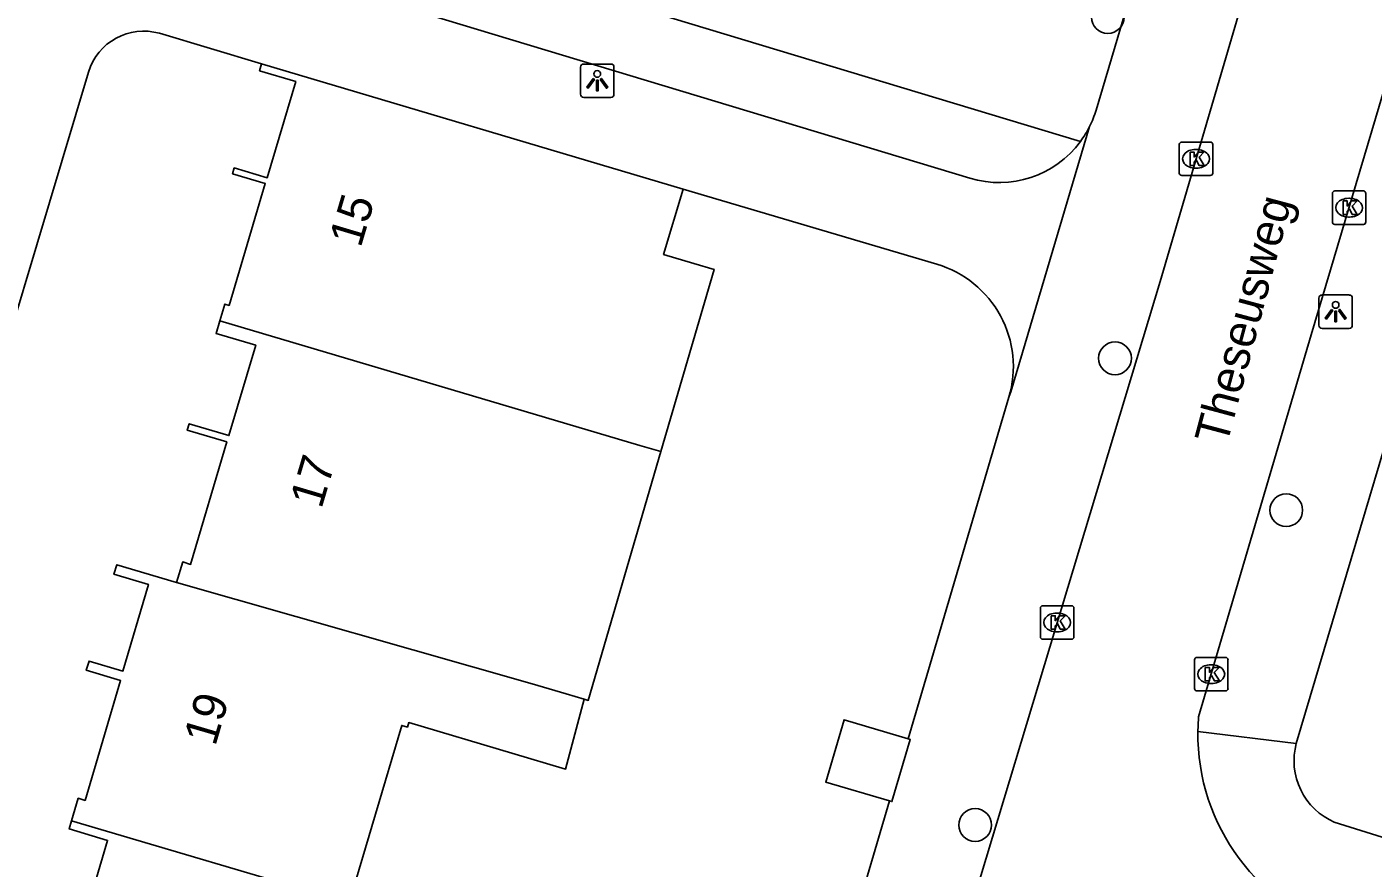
# Model space of a CAD drawing. Extents: x 162186 to 163152, y 385513 to 386513.
# Drawn here: x 162692.04 to 162732.25, y 386082.74 to 386107.85 of the extents above; entities that cross this region are included whole.
import ezdxf

# ---------------------------------------------------------------- set-up
doc = ezdxf.new("R2010")
doc.units = 0
for name, color, linetype in [('IMGEO_Boom', 7, 'Continuous'), ('IMGEO_Groenvoorziening', 7, 'Continuous'), ('IMGEO_Kolk', 7, 'Continuous'), ('IMGEO_Lichtpunt', 7, 'Continuous'), ('IMGEO_Openbare_ruimte_label', 7, 'Continuous'), ('IMGEO_Pand', 7, 'Continuous'), ('IMGEO_Pand_nummerreeks', 7, 'Continuous'), ('IMGEO_Rijbaan_lokaal_open', 7, 'Continuous'), ('IMGEO_Voetpad_open', 7, 'Continuous')]:
    doc.layers.add(name, color=color, linetype=linetype)

msp = doc.modelspace()

# ---------------------------------------------------------------- linework, layer by layer
at = {"layer": 'IMGEO_Boom'}
for centre in [(162724.33, 386108.149), (162724.546, 386097.96), (162729.661, 386093.425), (162720.367, 386084.025)]:
    msp.add_circle(centre, 0.489, dxfattribs=at)
at = {"layer": 'IMGEO_Groenvoorziening'}
msp.add_lwpolyline([(162701.905, 386126.5), (162697.912, 386113.179), (162697.874, 386112.633), (162698.083, 386112.243), (162698.513, 386111.989), (162723.511, 386104.431)], dxfattribs=at)
at = {"layer": 'IMGEO_Kolk'}
for p, q in [((162726.465, 386103.491), (162726.465, 386104.343)), ((162726.54, 386104.417), (162727.392, 386104.417)), ((162726.953, 386104.197), (162726.978, 386104.197)), ((162727.466, 386104.343), (162727.466, 386103.491)), ((162727.392, 386103.417), (162726.54, 386103.417)), ((162726.976, 386103.637), (162726.951, 386103.637)), ((162731.113, 386102.957), (162731.965, 386102.957)), ((162731.038, 386102.031), (162731.038, 386102.883)), ((162731.526, 386102.737), (162731.551, 386102.737)), ((162732.039, 386102.883), (162732.039, 386102.031)), ((162731.549, 386102.177), (162731.524, 386102.177)), ((162731.965, 386101.957), (162731.113, 386101.957)), ((162722.316, 386089.647), (162722.316, 386090.499)), ((162722.391, 386090.573), (162723.243, 386090.573)), ((162723.317, 386090.499), (162723.317, 386089.647)), ((162722.804, 386090.353), (162722.829, 386090.353)), ((162722.827, 386089.793), (162722.802, 386089.793)), ((162723.243, 386089.573), (162722.391, 386089.573)), ((162726.92, 386088.104), (162726.92, 386088.956)), ((162726.995, 386089.03), (162727.847, 386089.03)), ((162727.921, 386088.956), (162727.921, 386088.104)), ((162727.408, 386088.81), (162727.433, 386088.81)), ((162727.431, 386088.25), (162727.406, 386088.25)), ((162727.847, 386088.03), (162726.995, 386088.03))]:
    msp.add_line(p, q, dxfattribs=at)
for points in [[(162726.465, 386103.491), (162726.465, 386104.343)], [(162726.54, 386104.417), (162727.392, 386104.417)], [(162727.466, 386104.343), (162727.466, 386103.491)], [(162726.786, 386104.117), (162726.909, 386104.117), (162726.909, 386103.966), (162727.039, 386104.117), (162727.203, 386104.117), (162727.057, 386103.966), (162727.21, 386103.717), (162727.058, 386103.717), (162726.973, 386103.881), (162726.909, 386103.814), (162726.909, 386103.717), (162726.786, 386103.717), (162726.786, 386104.117)], [(162727.392, 386103.417), (162726.54, 386103.417)], [(162731.113, 386102.957), (162731.965, 386102.957)], [(162731.038, 386102.031), (162731.038, 386102.883)], [(162731.359, 386102.657), (162731.482, 386102.657), (162731.482, 386102.506), (162731.612, 386102.657), (162731.776, 386102.657), (162731.63, 386102.506), (162731.783, 386102.257), (162731.631, 386102.257), (162731.546, 386102.421), (162731.482, 386102.354), (162731.482, 386102.257), (162731.359, 386102.257), (162731.359, 386102.657)], [(162732.039, 386102.883), (162732.039, 386102.031)], [(162731.965, 386101.957), (162731.113, 386101.957)], [(162722.316, 386089.647), (162722.316, 386090.499)], [(162722.391, 386090.573), (162723.243, 386090.573)], [(162723.317, 386090.499), (162723.317, 386089.647)], [(162722.637, 386090.273), (162722.76, 386090.273), (162722.76, 386090.122), (162722.89, 386090.273), (162723.054, 386090.273), (162722.908, 386090.122), (162723.061, 386089.873), (162722.909, 386089.873), (162722.824, 386090.037), (162722.76, 386089.97), (162722.76, 386089.873), (162722.637, 386089.873), (162722.637, 386090.273)], [(162723.243, 386089.573), (162722.391, 386089.573)], [(162726.92, 386088.104), (162726.92, 386088.956)], [(162726.995, 386089.03), (162727.847, 386089.03)], [(162727.921, 386088.956), (162727.921, 386088.104)], [(162727.241, 386088.73), (162727.364, 386088.73), (162727.364, 386088.579), (162727.494, 386088.73), (162727.658, 386088.73), (162727.512, 386088.579), (162727.665, 386088.33), (162727.513, 386088.33), (162727.428, 386088.494), (162727.364, 386088.427), (162727.364, 386088.33), (162727.241, 386088.33), (162727.241, 386088.73)], [(162727.847, 386088.03), (162726.995, 386088.03)]]:
    msp.add_lwpolyline(points, dxfattribs=at)
for centre, start, end in [((162726.542, 386104.341), 91.552, 178.448), ((162726.542, 386104.341), 91.552, 178.448), ((162727.39, 386104.341), 1.552, 88.448), ((162727.39, 386104.341), 1.552, 88.448), ((162726.542, 386103.493), 181.552, 268.448), ((162726.542, 386103.493), 181.552, 268.448), ((162727.39, 386103.493), 271.552, 358.448), ((162727.39, 386103.493), 271.552, 358.448), ((162731.115, 386102.881), 91.552, 178.448), ((162731.115, 386102.881), 91.552, 178.448), ((162731.963, 386102.881), 1.552, 88.448), ((162731.963, 386102.881), 1.552, 88.448), ((162731.115, 386102.033), 181.552, 268.448), ((162731.115, 386102.033), 181.552, 268.448), ((162731.963, 386102.033), 271.552, 358.448), ((162731.963, 386102.033), 271.552, 358.448), ((162722.393, 386090.497), 91.552, 178.448), ((162722.393, 386090.497), 91.552, 178.448), ((162723.241, 386090.497), 1.552, 88.448), ((162723.241, 386090.497), 1.552, 88.448), ((162722.393, 386089.649), 181.552, 268.448), ((162722.393, 386089.649), 181.552, 268.448), ((162723.241, 386089.649), 271.552, 358.448), ((162723.241, 386089.649), 271.552, 358.448), ((162726.997, 386088.954), 91.552, 178.448), ((162726.997, 386088.954), 91.552, 178.448), ((162727.845, 386088.954), 1.552, 88.448), ((162727.845, 386088.954), 1.552, 88.448), ((162726.997, 386088.106), 181.552, 268.448), ((162726.997, 386088.106), 181.552, 268.448), ((162727.845, 386088.106), 271.552, 358.448), ((162727.845, 386088.106), 271.552, 358.448)]:
    msp.add_arc(centre, 0.0765, start, end, dxfattribs=at)
for centre, major_axis, ratio, start_param, end_param in [((162726.952, 386103.917), (-0.387, 0.002), 0.722429, 4.712389, 7.853982), ((162726.977, 386103.917), (-0.39, 0.002), 0.717154, 1.570796, 4.712389), ((162731.525, 386102.457), (-0.387, 0.002), 0.722429, 4.712389, 7.853982), ((162731.55, 386102.457), (-0.39, 0.002), 0.717154, 1.570796, 4.712389), ((162722.803, 386090.073), (-0.387, 0.002), 0.722429, 4.712389, 7.853982), ((162722.828, 386090.073), (-0.39, 0.002), 0.717154, 1.570796, 4.712389), ((162727.407, 386088.53), (-0.387, 0.002), 0.722429, 4.712389, 7.853982), ((162727.432, 386088.53), (-0.39, 0.002), 0.717154, 1.570796, 4.712389)]:
    msp.add_ellipse(centre, major_axis=major_axis, ratio=ratio, start_param=start_param, end_param=end_param, dxfattribs=at)
at = {"layer": 'IMGEO_Lichtpunt'}
for p, q in [((162708.582, 386106.651), (162708.582, 386105.844)), ((162708.582, 386106.651), (162708.582, 386105.844)), ((162709.484, 386106.746), (162708.676, 386106.746)), ((162709.484, 386106.746), (162708.676, 386106.746)), ((162709.578, 386105.844), (162709.578, 386106.651)), ((162709.578, 386105.844), (162709.578, 386106.651)), ((162708.676, 386105.75), (162709.484, 386105.75)), ((162708.676, 386105.75), (162709.484, 386105.75)), ((162730.638, 386099.755), (162730.638, 386098.948)), ((162730.638, 386099.755), (162730.638, 386098.948)), ((162731.54, 386099.85), (162730.732, 386099.85)), ((162731.54, 386099.85), (162730.732, 386099.85)), ((162731.634, 386098.948), (162731.634, 386099.755)), ((162731.634, 386098.948), (162731.634, 386099.755)), ((162730.732, 386098.854), (162731.54, 386098.854)), ((162730.732, 386098.854), (162731.54, 386098.854))]:
    msp.add_line(p, q, dxfattribs=at)
for points in [[(162708.956, 386106.315), (162708.995, 386106.287), (162708.807, 386106.025), (162708.769, 386106.052), (162708.956, 386106.315)], [(162709.058, 386106.267), (162709.105, 386106.267), (162709.105, 386105.945), (162709.058, 386105.945), (162709.058, 386106.267)], [(162709.168, 386106.287), (162709.206, 386106.314), (162709.393, 386106.052), (162709.354, 386106.024), (162709.168, 386106.287)], [(162731.012, 386099.419), (162731.051, 386099.391), (162730.863, 386099.129), (162730.825, 386099.156), (162731.012, 386099.419)], [(162731.114, 386099.371), (162731.161, 386099.371), (162731.161, 386099.049), (162731.114, 386099.049), (162731.114, 386099.371)], [(162731.224, 386099.391), (162731.262, 386099.418), (162731.449, 386099.156), (162731.41, 386099.128), (162731.224, 386099.391)]]:
    msp.add_lwpolyline(points, dxfattribs=at)
for centre in [(162709.081, 386106.449), (162731.137, 386099.553)]:
    msp.add_circle(centre, 0.0994, dxfattribs=at)
for centre, start, end in [((162708.676, 386106.651), 90, 180), ((162708.676, 386106.651), 90, 180), ((162709.484, 386106.651), 0, 90), ((162709.484, 386106.651), 0, 90), ((162708.676, 386105.844), 180, 270), ((162708.676, 386105.844), 180, 270), ((162709.484, 386105.844), 270, 0), ((162709.484, 386105.844), 270, 360), ((162730.732, 386099.755), 90, 180), ((162730.732, 386099.755), 90, 180), ((162731.54, 386099.755), 0, 90), ((162731.54, 386099.755), 0, 90), ((162730.732, 386098.948), 180, 270), ((162730.732, 386098.948), 180, 270), ((162731.54, 386098.948), 270, 0), ((162731.54, 386098.948), 270, 360)]:
    msp.add_arc(centre, 0.0946, start, end, dxfattribs=at)
at = {"layer": 'IMGEO_Pand'}
for points in [[(162699.055, 386106.75), (162698.993, 386106.543), (162700.075, 386106.222), (162699.222, 386103.349), (162698.236, 386103.642), (162698.185, 386103.471), (162699.162, 386103.181), (162698.081, 386099.539), (162697.951, 386099.578), (162697.802, 386099.075)], [(162699.055, 386106.75), (162711.642, 386103.012)], [(162710.979, 386095.176), (162712.568, 386100.614), (162711.963, 386100.795), (162711.063, 386101.062), (162711.642, 386103.012)], [(162697.802, 386099.075), (162697.692, 386098.702), (162698.877, 386098.351), (162698.078, 386095.654), (162696.892, 386096.006), (162696.835, 386095.814), (162698.015, 386095.464), (162696.933, 386091.807), (162696.7, 386091.879), (162696.51, 386091.27)], [(162697.802, 386099.075), (162710.353, 386095.361), (162710.979, 386095.176)], [(162708.688, 386087.783), (162708.81, 386087.747), (162710.979, 386095.176)], [(162696.51, 386091.27), (162694.727, 386091.798), (162694.643, 386091.513), (162695.675, 386091.207), (162694.909, 386088.623), (162693.9, 386088.922), (162693.817, 386088.644), (162694.843, 386088.34), (162693.783, 386084.761), (162693.576, 386084.822), (162693.378, 386084.153)], [(162708.688, 386087.783), (162708.155, 386087.94), (162707.139, 386088.24), (162696.51, 386091.27)], [(162701.668, 386081.701), (162703.238, 386086.998), (162703.409, 386086.947), (162703.45, 386087.085), (162706.527, 386086.173), (162708.135, 386085.696), (162708.688, 386087.783)], [(162718.363, 386086.601), (162716.455, 386087.166), (162715.905, 386085.309), (162717.814, 386084.744)], [(162717.814, 386084.744), (162717.88, 386084.724), (162718.43, 386086.581), (162718.363, 386086.601)], [(162693.378, 386084.153), (162693.306, 386083.908), (162694.455, 386083.567), (162693.693, 386080.996), (162692.549, 386081.335), (162692.489, 386081.131), (162693.638, 386080.791), (162692.562, 386077.157), (162692.304, 386077.233), (162692.099, 386076.541)], [(162701.668, 386081.701), (162693.378, 386084.153)]]:
    msp.add_lwpolyline(points, dxfattribs=at)
at = {"layer": 'IMGEO_Rijbaan_lokaal_open'}
for points in [[(162717.243, 386071.595), (162725.891, 386100.255), (162730.846, 386117.114)], [(162735.486, 386115.734), (162730.41, 386098.664), (162727.044, 386087.256)], [(162727.023, 386086.818), (162729.962, 386086.464)], [(162735.074, 386082.862), (162731.096, 386084.112), (162730.945, 386084.185), (162730.791, 386084.277), (162730.647, 386084.381), (162730.512, 386084.498), (162730.389, 386084.627), (162730.277, 386084.766), (162730.178, 386084.915), (162730.093, 386085.072), (162730.023, 386085.236), (162729.967, 386085.406), (162729.927, 386085.579), (162729.902, 386085.756), (162729.893, 386085.934), (162729.9, 386086.113), (162729.923, 386086.29), (162729.962, 386086.464)]]:
    msp.add_lwpolyline(points, dxfattribs=at)
for centre, radius, start, end in [((162732.373, 386086.781), 5.35, 174.9062, 179.6039), ((162733.219, 386086.736), 6.197, 179.2391, 254.2273)]:
    msp.add_arc(centre, radius, start, end, dxfattribs=at)
at = {"layer": 'IMGEO_Voetpad_open'}
for points in [[(162729.962, 386086.464), (162748.726, 386149.462), (162748.746, 386149.525)], [(162726.491, 386113.829), (162723.98, 386105.37)], [(162720.212, 386103.338), (162697.883, 386110.09)], [(162696.003, 386107.663), (162699.055, 386106.75)], [(162675.165, 386044.035), (162690.004, 386093.566), (162693.881, 386106.506)], [(162723.787, 386104.88), (162721.438, 386096.954), (162721.377, 386096.799)], [(162711.642, 386103.012), (162719.228, 386100.767)], [(162721.377, 386096.799), (162718.363, 386086.601)], [(162717.814, 386084.744), (162715.637, 386077.378)]]:
    msp.add_lwpolyline(points, dxfattribs=at)
for centre, radius, start, end in [((162695.534, 386106), 1.728, 74.2389, 162.9631), ((162721.018, 386106.254), 3.091, 333.6152, 343.3881), ((162721.173, 386106.177), 2.918, 323.2398, 333.6021), ((162721.086, 386106.226), 3.018, 253.1708, 323.4905), ((162718.322, 386097.71), 3.188, 343.3934, 73.485)]:
    msp.add_arc(centre, radius, start, end, dxfattribs=at)

# ---------------------------------------------------------------- texts
at = {"layer": 'IMGEO_Openbare_ruimte_label'}
msp.add_text('Theseusweg', height=1, rotation=75.0464, dxfattribs=at).set_placement((162727.881, 386095.33))
at = {"layer": 'IMGEO_Pand_nummerreeks'}
for s, rotation, p in [('15', 73.3844, (162702.011, 386101.237)), ('17', 73.4532, (162700.84, 386093.441)), ('19', 73.6423, (162697.669, 386086.354))]:
    msp.add_text(s, height=1, rotation=rotation, dxfattribs=at).set_placement(p)

doc.saveas('drawing.dxf')
